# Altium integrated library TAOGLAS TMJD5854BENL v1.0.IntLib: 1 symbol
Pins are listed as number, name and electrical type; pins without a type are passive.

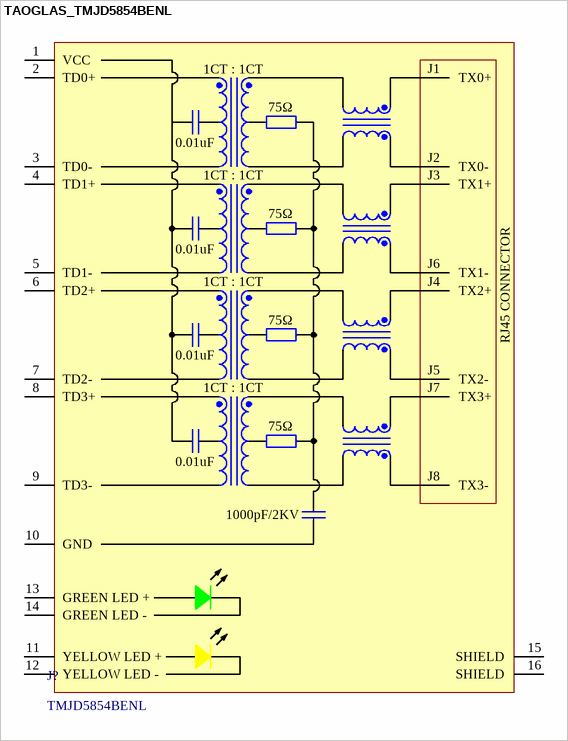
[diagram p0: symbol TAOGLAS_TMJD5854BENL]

## TAOGLAS_TMJD5854BENL
designator J?, comment TMJD5854BENL
RJ45 connector with integrated magnetics 1G Base-T Vertical with step THT mount and LEDs; ComponentLibStatus: Created; MFG: Taoglas; Temp_High: +85C; Temp_Low: -40C
footprint TAOGLAS_TMJD5854BENL (RJ45 connector with integrated magnetics 1G Base-T Vertical with step THT mount and LEDs)
pins: 1 VCC, 2 TD0+, 3 TD0-, 4 TD1+, 5 TD1-, 6 TD2+, 7 TD2-, 8 TD3+, 9 TD3-, 10 GND, 11 YELLOW LED +, 12 YELLOW LED -, 13 GREEN LED +, 14 GREEN LED -, 15 SHIELD, 16 SHIELD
